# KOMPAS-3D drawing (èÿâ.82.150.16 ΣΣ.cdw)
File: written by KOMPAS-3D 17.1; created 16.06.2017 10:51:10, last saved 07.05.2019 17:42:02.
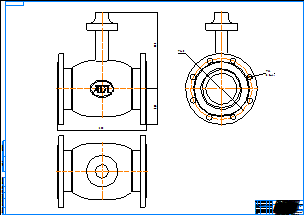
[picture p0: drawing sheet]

Sheet 1: A0, landscape

Title block, sheet 1: name: КШГ.82.150.16 фф; material: Внимание! Данный продукт является объектом авторского права ООО «Торговый Дом АДЛ». / Запрещается изменение, копирование, распространение / (в том числе путем копирования на другие сайты и ресурсы в Интернете) / или любое иное использование информации и объектов без предварительного / согласия правообладателя (ООО «Торговый Дом АДЛ»).; scale: 1:1; sheets: 1; organisation: ООО "Торговый дом АДЛ"; sheet format: A0; stored path: C:\Users\tra\Desktop\2д чертежи\Шаровые краны БИВАЛ\КШ_Бивал_серия_82_85\KOMPAS 2D\КШГ.82.150.16 фф.cdw

Views: Спереди 1, Проекционный вид 2, Проекционный вид 3
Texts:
  Klimkovich
  ADL
Dimensions and other numbers on the sheet: 350; 300; 140; 240; 22; 8 Отв.; 1:1; 1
